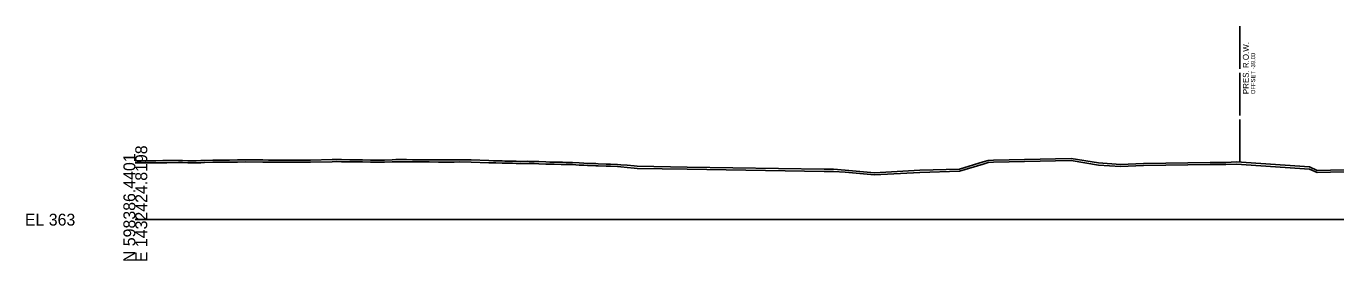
# Model space of a CAD drawing. Extents: x -26 to 2203, y -10 to 12201.
# Drawn here: x -25.7 to 282.6, y 4990.3 to 5045.6 of the extents above; entities that cross this region are included whole.
import ezdxf

# ---------------------------------------------------------------- set-up
doc = ezdxf.new("R2010")
doc.units = 0
for name, color, linetype in [('DESIGN - SHEET - Light Grid', 7, 'Continuous'), ('SURVEY - GROUND - Bottom of Topsoil Layer', 7, 'Continuous'), ('SURVEY - GROUND - Top of Ground', 7, 'Continuous'), ('SURVEY - PROPERTY - ROW Lines', 7, 'Continuous'), ('SURVEY - PROPERTY - ROW Lines Text', 7, 'Continuous')]:
    doc.layers.add(name, color=color, linetype=linetype)

msp = doc.modelspace()

# ---------------------------------------------------------------- linework, layer by layer
at = {"layer": 'DESIGN - SHEET - Light Grid'}
msp.add_line((0, 5000), (300, 5000), dxfattribs=at)
at = {"layer": 'SURVEY - GROUND - Bottom of Topsoil Layer'}
for p, q in [((0, 5013.34), (4, 5013.36)), ((4, 5013.36), (4.83, 5013.38)), ((4.83, 5013.38), (6.47, 5013.41)), ((6.47, 5013.41), (7.44, 5013.4)), ((7.44, 5013.4), (10.14, 5013.46)), ((10.14, 5013.46), (11.13, 5013.42)), ((11.13, 5013.42), (12.36, 5013.37)), ((12.36, 5013.37), (12.79, 5013.35)), ((12.79, 5013.35), (14.32, 5013.36)), ((14.32, 5013.36), (15.44, 5013.4)), ((15.44, 5013.4), (16.28, 5013.42)), ((16.28, 5013.42), (18.24, 5013.52)), ((18.24, 5013.52), (18.66, 5013.52)), ((18.66, 5013.52), (20.43, 5013.5)), ((20.43, 5013.5), (22.16, 5013.52)), ((22.16, 5013.52), (24.02, 5013.55)), ((24.02, 5013.55), (26.04, 5013.62)), ((26.04, 5013.62), (30.05, 5013.55)), ((30.05, 5013.55), (31.34, 5013.52)), ((31.34, 5013.52), (31.96, 5013.52)), ((31.96, 5013.52), (33.99, 5013.52)), ((33.99, 5013.52), (35.88, 5013.53)), ((35.88, 5013.53), (36.64, 5013.54)), ((36.64, 5013.54), (37.84, 5013.53)), ((37.84, 5013.53), (39.29, 5013.5)), ((39.29, 5013.5), (41.24, 5013.53)), ((41.24, 5013.53), (46.35, 5013.64)), ((46.35, 5013.64), (47.25, 5013.66)), ((47.25, 5013.66), (48.53, 5013.63)), ((48.53, 5013.63), (50.51, 5013.6)), ((50.51, 5013.6), (53.52, 5013.58)), ((53.52, 5013.58), (55.36, 5013.53)), ((55.36, 5013.53), (56.29, 5013.52)), ((56.29, 5013.52), (57.44, 5013.5)), ((57.44, 5013.5), (57.85, 5013.51)), ((57.85, 5013.51), (58.69, 5013.54)), ((58.69, 5013.54), (60.5, 5013.6)), ((60.5, 5013.6), (61.36, 5013.63)), ((61.36, 5013.63), (63.32, 5013.63)), ((63.32, 5013.63), (63.82, 5013.63)), ((63.82, 5013.63), (65.28, 5013.62)), ((65.28, 5013.62), (65.8, 5013.62)), ((65.8, 5013.62), (67.24, 5013.61)), ((67.24, 5013.61), (68.45, 5013.58)), ((68.45, 5013.58), (69.2, 5013.59)), ((69.2, 5013.59), (71.34, 5013.55)), ((71.34, 5013.55), (75.09, 5013.56)), ((75.09, 5013.56), (76.39, 5013.58)), ((76.39, 5013.58), (79.05, 5013.57)), ((79.05, 5013.57), (83.24, 5013.41)), ((83.24, 5013.41), (84.35, 5013.37)), ((84.35, 5013.37), (84.89, 5013.35)), ((84.89, 5013.35), (86.4, 5013.31)), ((199.57, 5013.09), (200.81, 5013.45)), ((200.81, 5013.45), (202.05, 5013.51)), ((202.05, 5013.51), (220.36, 5013.9)), ((220.36, 5013.9), (226.77, 5012.86)), ((86.4, 5013.31), (87, 5013.29)), ((87, 5013.29), (88.81, 5013.27)), ((88.81, 5013.27), (89.66, 5013.24)), ((89.66, 5013.24), (90.77, 5013.23)), ((90.77, 5013.23), (92.31, 5013.24)), ((92.31, 5013.24), (92.73, 5013.23)), ((92.73, 5013.23), (93.92, 5013.19)), ((93.92, 5013.19), (94.96, 5013.17)), ((94.96, 5013.17), (96.65, 5013.09)), ((96.65, 5013.09), (97.61, 5013.03)), ((97.61, 5013.03), (98.61, 5013.03)), ((98.61, 5013.03), (100.26, 5013)), ((100.26, 5013), (100.57, 5013)), ((100.57, 5013), (101.45, 5012.98)), ((101.45, 5012.98), (102.53, 5012.96)), ((102.53, 5012.96), (102.91, 5012.95)), ((102.91, 5012.95), (104.49, 5012.84)), ((104.49, 5012.84), (105.56, 5012.8)), ((105.56, 5012.8), (106.45, 5012.76)), ((106.45, 5012.76), (108.41, 5012.69)), ((108.41, 5012.69), (108.98, 5012.67)), ((108.98, 5012.67), (110.86, 5012.6)), ((110.86, 5012.6), (111.89, 5012.57)), ((111.89, 5012.57), (113.51, 5012.49)), ((113.51, 5012.49), (114.29, 5012.43)), ((114.29, 5012.43), (115.81, 5012.31)), ((115.81, 5012.31), (117.44, 5012.15)), ((117.44, 5012.15), (118.15, 5012.08)), ((118.15, 5012.08), (129.94, 5011.86)), ((129.94, 5011.86), (162.14, 5011.37)), ((162.14, 5011.37), (164.39, 5011.35)), ((164.39, 5011.35), (167.11, 5011.18)), ((167.11, 5011.18), (174, 5010.53)), ((174, 5010.53), (184.73, 5011.14)), ((184.73, 5011.14), (194, 5011.39)), ((194, 5011.39), (199.57, 5013.09)), ((226.77, 5012.86), (231.91, 5012.52)), ((231.91, 5012.52), (237.33, 5012.72)), ((237.33, 5012.72), (253.06, 5012.97)), ((253.06, 5012.97), (256.77, 5012.98)), ((256.77, 5012.98), (259.28, 5013.1)), ((259.28, 5013.1), (276.43, 5011.92)), ((276.43, 5011.92), (278.26, 5011.09)), ((278.26, 5011.09), (287.76, 5011.32))]:
    msp.add_line(p, q, dxfattribs=at)
at = {"layer": 'SURVEY - GROUND - Top of Ground'}
for p, q in [((0, 5013.84), (4, 5013.86)), ((4, 5013.86), (4.83, 5013.88)), ((4.83, 5013.88), (6.47, 5013.91)), ((6.47, 5013.91), (7.44, 5013.9)), ((7.44, 5013.9), (10.14, 5013.96)), ((10.14, 5013.96), (11.13, 5013.92)), ((11.13, 5013.92), (12.36, 5013.87)), ((12.36, 5013.87), (12.79, 5013.85)), ((12.79, 5013.85), (14.32, 5013.86)), ((14.32, 5013.86), (15.44, 5013.9)), ((15.44, 5013.9), (16.28, 5013.92)), ((16.28, 5013.92), (18.24, 5014.02)), ((18.24, 5014.02), (18.66, 5014.02)), ((18.66, 5014.02), (20.43, 5014)), ((20.43, 5014), (22.16, 5014.02)), ((22.16, 5014.02), (24.02, 5014.05)), ((24.02, 5014.05), (26.04, 5014.12)), ((26.04, 5014.12), (30.05, 5014.05)), ((30.05, 5014.05), (31.34, 5014.02)), ((31.34, 5014.02), (31.96, 5014.02)), ((31.96, 5014.02), (33.99, 5014.02)), ((33.99, 5014.02), (35.88, 5014.03)), ((35.88, 5014.03), (36.64, 5014.04)), ((36.64, 5014.04), (37.84, 5014.03)), ((37.84, 5014.03), (39.29, 5014)), ((39.29, 5014), (41.24, 5014.03)), ((41.24, 5014.03), (46.35, 5014.14)), ((46.35, 5014.14), (47.25, 5014.16)), ((47.25, 5014.16), (48.53, 5014.13)), ((48.53, 5014.13), (50.51, 5014.1)), ((50.51, 5014.1), (53.52, 5014.08)), ((53.52, 5014.08), (55.36, 5014.03)), ((55.36, 5014.03), (56.29, 5014.02)), ((56.29, 5014.02), (57.44, 5014)), ((57.44, 5014), (57.85, 5014.01)), ((57.85, 5014.01), (58.69, 5014.04)), ((58.69, 5014.04), (60.5, 5014.1)), ((60.5, 5014.1), (61.36, 5014.13)), ((61.36, 5014.13), (63.32, 5014.13)), ((63.32, 5014.13), (63.82, 5014.13)), ((63.82, 5014.13), (65.28, 5014.12)), ((65.28, 5014.12), (65.8, 5014.12)), ((65.8, 5014.12), (67.24, 5014.11)), ((67.24, 5014.11), (68.45, 5014.08)), ((68.45, 5014.08), (69.2, 5014.09)), ((69.2, 5014.09), (71.34, 5014.05)), ((71.34, 5014.05), (75.09, 5014.06)), ((75.09, 5014.06), (76.39, 5014.08)), ((76.39, 5014.08), (79.05, 5014.07)), ((79.05, 5014.07), (83.24, 5013.91)), ((83.24, 5013.91), (84.35, 5013.87)), ((84.35, 5013.87), (84.89, 5013.85)), ((84.89, 5013.85), (86.4, 5013.81)), ((86.4, 5013.81), (87, 5013.79)), ((87, 5013.79), (88.81, 5013.77)), ((88.81, 5013.77), (89.66, 5013.74)), ((89.66, 5013.74), (90.77, 5013.73)), ((90.77, 5013.73), (92.31, 5013.74)), ((92.31, 5013.74), (92.73, 5013.73)), ((92.73, 5013.73), (93.92, 5013.69)), ((93.92, 5013.69), (94.96, 5013.67)), ((94.96, 5013.67), (96.65, 5013.59)), ((96.65, 5013.59), (97.61, 5013.53)), ((97.61, 5013.53), (98.61, 5013.53)), ((98.61, 5013.53), (100.26, 5013.5)), ((100.26, 5013.5), (100.57, 5013.5)), ((100.57, 5013.5), (101.45, 5013.48)), ((101.45, 5013.48), (102.53, 5013.46)), ((102.53, 5013.46), (102.91, 5013.45)), ((102.91, 5013.45), (104.49, 5013.34)), ((104.49, 5013.34), (105.56, 5013.3)), ((194, 5011.89), (199.57, 5013.59)), ((199.57, 5013.59), (200.81, 5013.95)), ((200.81, 5013.95), (202.05, 5014.01)), ((202.05, 5014.01), (220.36, 5014.4)), ((220.36, 5014.4), (226.77, 5013.36)), ((226.77, 5013.36), (231.91, 5013.02)), ((237.33, 5013.22), (253.06, 5013.47)), ((253.06, 5013.47), (256.77, 5013.48)), ((256.77, 5013.48), (259.28, 5013.6)), ((259.28, 5013.6), (276.43, 5012.42)), ((105.56, 5013.3), (106.45, 5013.26)), ((106.45, 5013.26), (108.41, 5013.19)), ((108.41, 5013.19), (108.98, 5013.17)), ((108.98, 5013.17), (110.86, 5013.1)), ((110.86, 5013.1), (111.89, 5013.07)), ((111.89, 5013.07), (113.51, 5012.99)), ((113.51, 5012.99), (114.29, 5012.93)), ((114.29, 5012.93), (115.81, 5012.81)), ((115.81, 5012.81), (117.44, 5012.65)), ((117.44, 5012.65), (118.15, 5012.58)), ((118.15, 5012.58), (129.94, 5012.36)), ((129.94, 5012.36), (162.14, 5011.87)), ((162.14, 5011.87), (164.39, 5011.85)), ((164.39, 5011.85), (167.11, 5011.68)), ((167.11, 5011.68), (174, 5011.03)), ((174, 5011.03), (184.73, 5011.64)), ((184.73, 5011.64), (194, 5011.89)), ((231.91, 5013.02), (237.33, 5013.22)), ((276.43, 5012.42), (278.26, 5011.59)), ((278.26, 5011.59), (287.76, 5011.82))]:
    msp.add_line(p, q, dxfattribs=at)
at = {"layer": 'SURVEY - PROPERTY - ROW Lines'}
for p, q in [((260, 5035.55), (260, 5045.55)), ((260, 5024.55), (260, 5034.55)), ((260, 5013.55), (260, 5023.55))]:
    msp.add_line(p, q, dxfattribs=at)

# ---------------------------------------------------------------- texts
at = {"layer": 'DESIGN - SHEET - Light Grid'}
for s, p in [('E 1432424.8198', (2.8, 4990)), ('N 598386.4401', (0, 4990))]:
    msp.add_text(s, height=2.8, rotation=90, dxfattribs=at).set_placement(p)
msp.add_text('EL 363', height=2.8, dxfattribs=at).set_placement((-26, 4998.6))
at = {"layer": 'SURVEY - PROPERTY - ROW Lines Text'}
for s, height, p in [('PRES. R.O.W.', 1.4, (262.15, 5029.55)), ('OFFSET -39.00', 1, (263.65, 5029.55))]:
    msp.add_text(s, height=height, rotation=90, dxfattribs=at).set_placement(p)

doc.saveas('drawing.dxf')
